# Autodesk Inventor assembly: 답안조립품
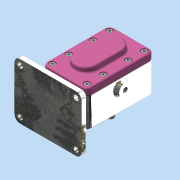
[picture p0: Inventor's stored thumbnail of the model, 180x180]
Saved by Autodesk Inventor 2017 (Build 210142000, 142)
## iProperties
Part Number: 답안조립품
Material: 일반
Document SubType Name: Assembly
Designer: MRC
Author: MRC
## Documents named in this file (11)
- C:\Users\MRC\Desktop\700407V1040\답안조립품.iam
- C:\Users\MRC\Desktop\700407V1040\Ű 6 x 6 x 18.ipt
- C:\Users\MRC\Desktop\700407V1040\개스킷.ipt
- C:\Users\MRC\Desktop\700407V1040\메인축.ipt
- C:\Users\MRC\Desktop\700407V1040\베어링부시.ipt
- C:\Users\MRC\Desktop\700407V1040\본체.ipt
- C:\Users\MRC\Desktop\700407V1040\볼트 M5.ipt
- C:\Users\MRC\Desktop\700407V1040\서브축.ipt
- C:\Users\MRC\Desktop\700407V1040\스퍼기어.ipt
- C:\Users\MRC\Desktop\700407V1040\오일 실 16 28 7.ipt
- C:\Users\MRC\Desktop\700407V1040\커버.ipt
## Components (3 placed, 2 different names)
1. Ű 6 x 6 x 18:1
2. 개스킷:1
3. Ű 6 x 6 x 18:2
